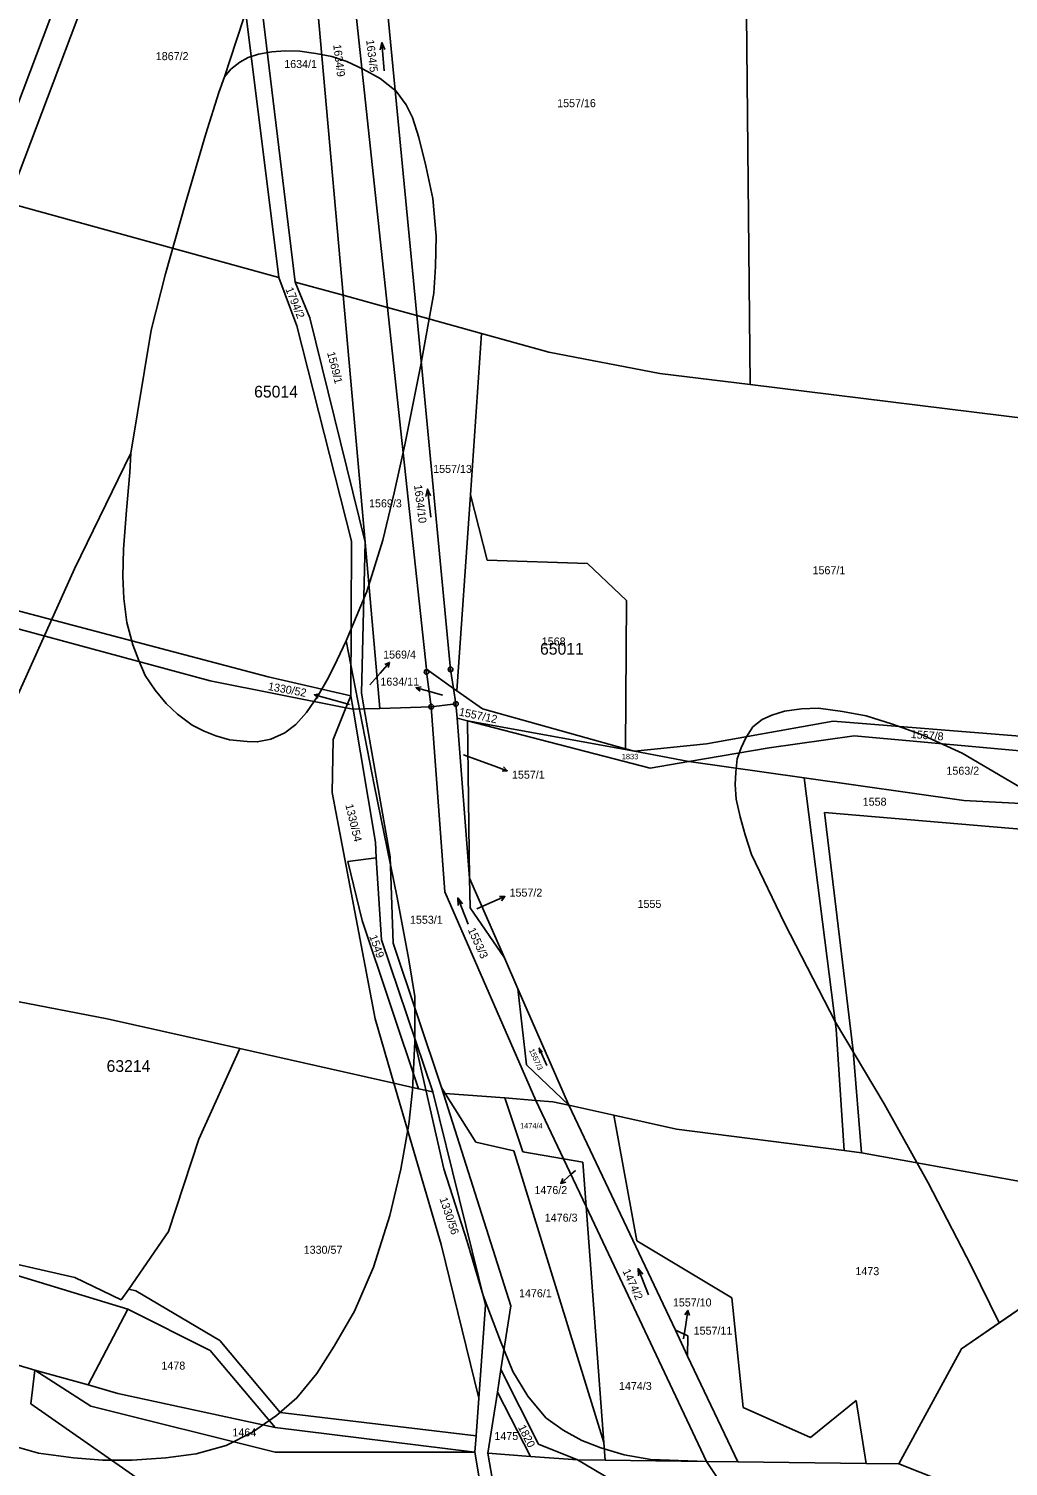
# Model space of a CAD drawing. Extents: x -546762 to -540209, y -1046851 to -1035694.
# Drawn here: x -542518.2 to -542310.2, y -1041335.5 to -1041030.2 of the extents above; entities that cross this region are included whole.
import ezdxf

# ---------------------------------------------------------------- set-up
doc = ezdxf.new("R2010")
doc.units = 0
for name, color, linetype in [('Vrstva 1', 7, 'Continuous'), ('Vrstva 16', 7, 'Continuous'), ('Vrstva 18', 7, 'Continuous'), ('Vrstva 24', 7, 'Continuous'), ('Vrstva 25', 7, 'Continuous'), ('Vrstva 52', 7, 'Continuous'), ('Vrstva 53', 7, 'Continuous'), ('Vrstva 6', 7, 'Continuous')]:
    doc.layers.add(name, color=color, linetype=linetype)

msp = doc.modelspace()

# ---------------------------------------------------------------- linework, layer by layer
at = {"layer": 'Vrstva 1'}
msp.add_line((-542445.44, -1040991.01), (-542435.86, -1041091.16), dxfattribs=at)
for points in [[(-542465.12, -1041083.07), (-542476.38, -1040992.91)], [(-542461.68, -1041084.02), (-542472.7, -1040992.93)], [(-542459.8, -1040992.99), (-542451.48, -1041086.84)], [(-542442.07, -1041089.44), (-542452.43, -1040992.98)], [(-542502.42, -1040998.17), (-542527.98, -1041065.76)], [(-542522.68, -1041067.22), (-542498.43, -1041002.85)], [(-542366.02, -1041005.65), (-542365.01, -1041105.81)], [(-542465.12, -1041083.07), (-542522.68, -1041067.22)], [(-542465.12, -1041083.07), (-542461.35, -1041093.33)], [(-542461.68, -1041084.02), (-542451.48, -1041086.84)], [(-542461.68, -1041084.02), (-542458.58, -1041091.62)], [(-542451.48, -1041086.84), (-542442.07, -1041089.44)], [(-542451.48, -1041086.84), (-542446.83, -1041139.28)], [(-542442.07, -1041089.44), (-542435.86, -1041091.16)], [(-542433.81, -1041166.25), (-542442.07, -1041089.44)], [(-542461.35, -1041093.33), (-542449.71, -1041139.07)], [(-542458.58, -1041091.62), (-542446.83, -1041139.28)], [(-542435.86, -1041091.16), (-542428.67, -1041166.28)], [(-542449.71, -1041139.07), (-542449.85, -1041171.87)], [(-542446.83, -1041139.28), (-542447.57, -1041171.34)], [(-542446.83, -1041139.28), (-542443.7, -1041174.57)], [(-542433.81, -1041166.25), (-542428.03, -1041170.33)], [(-542433.75, -1041166.83), (-542433.81, -1041166.25)], [(-542433.75, -1041166.83), (-542432.78, -1041174.22)], [(-542428.03, -1041170.33), (-542428.67, -1041166.28)], [(-542427.52, -1041173.6), (-542428.03, -1041170.33)], [(-542449.85, -1041171.87), (-542449.37, -1041174.76)], [(-542447.57, -1041171.34), (-542446.99, -1041174.68)], [(-542446.99, -1041174.68), (-542449.37, -1041174.76)], [(-542449.37, -1041174.76), (-542444.64, -1041202.96)], [(-542443.7, -1041174.57), (-542446.99, -1041174.68)], [(-542446.99, -1041174.68), (-542441.5, -1041206.12)], [(-542432.78, -1041174.22), (-542443.7, -1041174.57)], [(-542432.78, -1041174.22), (-542427.52, -1041173.6)], [(-542432.78, -1041174.22), (-542429.91, -1041213.54)], [(-542427.52, -1041173.6), (-542427.28, -1041176.61)], [(-542427.28, -1041176.61), (-542424.63, -1041210.6)], [(-542444.64, -1041202.96), (-542444.44, -1041206.3)], [(-542450.49, -1041207.08), (-542444.44, -1041206.3)], [(-542447.43, -1041219.58), (-542450.49, -1041207.08)], [(-542444.44, -1041206.3), (-542443.37, -1041223.72)], [(-542440.88, -1041224.45), (-542441.5, -1041206.12)], [(-542424.63, -1041210.6), (-542424.54, -1041216.94)], [(-542424.63, -1041210.6), (-542417.24, -1041227.53)], [(-542429.91, -1041213.54), (-542410.53, -1041257.81)], [(-542424.54, -1041216.94), (-542417.24, -1041227.53)], [(-542447.43, -1041219.58), (-542435.45, -1041255.33)], [(-542443.37, -1041223.72), (-542432.45, -1041256)], [(-542440.88, -1041224.45), (-542430.58, -1041255.09)], [(-542417.24, -1041227.53), (-542414.37, -1041234.11)], [(-542412.55, -1041250.28), (-542414.37, -1041234.11)], [(-542414.37, -1041234.11), (-542403.56, -1041258.84)], [(-542501.61, -1041240.47), (-542526.92, -1041235.63)], [(-542473.45, -1041246.8), (-542501.61, -1041240.47)], [(-542473.45, -1041246.8), (-542482.11, -1041266.04)], [(-542403.56, -1041258.84), (-542412.55, -1041250.28)], [(-542432.45, -1041256), (-542435.45, -1041255.33)], [(-542430.58, -1041255.09), (-542415.87, -1041301.43)], [(-542429.81, -1041256.32), (-542430.58, -1041255.09)], [(-542432.45, -1041256), (-542421.27, -1041301.29)], [(-542429.81, -1041256.32), (-542417.16, -1041257.3)], [(-542423.31, -1041266.65), (-542429.81, -1041256.32)], [(-542417.16, -1041257.3), (-542410.53, -1041257.81)], [(-542417.16, -1041257.3), (-542413.31, -1041268.71)], [(-542410.53, -1041257.81), (-542406.92, -1041258.09)], [(-542410.53, -1041257.81), (-542404.68, -1041270.2)], [(-542406.92, -1041258.09), (-542403.56, -1041258.84)], [(-542403.56, -1041258.84), (-542380.93, -1041306.59)], [(-542482.11, -1041266.04), (-542488.54, -1041285.62)], [(-542423.31, -1041266.65), (-542415.21, -1041268.54)], [(-542415.21, -1041268.54), (-542396.14, -1041330.47)], [(-542404.68, -1041270.2), (-542413.31, -1041268.71)], [(-542400.59, -1041270.9), (-542404.68, -1041270.2)], [(-542404.68, -1041270.2), (-542399.88, -1041280.36)], [(-542400.59, -1041270.9), (-542399.88, -1041280.36)], [(-542399.88, -1041280.36), (-542396.14, -1041330.47)], [(-542399.88, -1041280.36), (-542374.33, -1041334.47)], [(-542488.54, -1041285.62), (-542497.03, -1041297.9)], [(-542521.22, -1041292.55), (-542508.43, -1041295.42)], [(-542508.43, -1041295.42), (-542498.6, -1041300.18)], [(-542320.17, -1041310.54), (-542295.33, -1041293.52)], [(-542497.03, -1041297.9), (-542498.6, -1041300.18)], [(-542421.27, -1041301.29), (-542422.69, -1041321.03)], [(-542415.87, -1041301.43), (-542417.97, -1041314.94)], [(-542380.93, -1041306.59), (-542378.32, -1041312.1)], [(-542333.5, -1041335), (-542320.17, -1041310.54)], [(-542378.32, -1041312.1), (-542367.67, -1041334.56)], [(-542417.97, -1041314.94), (-542418.72, -1041319.77)], [(-542417.97, -1041314.94), (-542410, -1041330.82)], [(-542418.72, -1041319.77), (-542420.74, -1041332.76)], [(-542418.72, -1041319.77), (-542411.7, -1041333.4)], [(-542422.69, -1041321.03), (-542423.26, -1041329.04)], [(-542423.26, -1041329.04), (-542423.51, -1041332.52)], [(-542410, -1041330.82), (-542401.69, -1041334.11)], [(-542396.14, -1041330.47), (-542395.87, -1041334.19)], [(-542423.51, -1041332.52), (-542417.02, -1041371.37)], [(-542411.7, -1041333.4), (-542420.74, -1041332.76)], [(-542420.74, -1041332.76), (-542414.26, -1041370.41)], [(-542401.69, -1041334.11), (-542411.7, -1041333.4)], [(-542395.87, -1041334.19), (-542401.69, -1041334.11)], [(-542374.33, -1041334.47), (-542395.87, -1041334.19)], [(-542367.67, -1041334.56), (-542374.33, -1041334.47)], [(-542374.33, -1041334.47), (-542345.88, -1041377.29)], [(-542340.44, -1041334.91), (-542367.67, -1041334.56)], [(-542333.5, -1041335), (-542340.44, -1041334.91)]]:
    msp.add_lwpolyline(points, dxfattribs=at)
at = {"layer": 'Vrstva 16'}
for p, q in [((-542443.59, -1041167.06), (-542441.61, -1041164.81)), ((-542433.09, -1041171.01), (-542435.98, -1041170.19)), ((-542454.7, -1041172.47), (-542457.59, -1041171.65)), ((-542419.45, -1041186.76), (-542416.63, -1041187.79)), ((-542419.89, -1041215.74), (-542417.14, -1041214.54)), ((-542403.03, -1041273.46), (-542405.28, -1041275.44)), ((-542378.73, -1041305.37), (-542378.25, -1041302.41))]:
    msp.add_line(p, q, dxfattribs=at)
for points in [[(-542445.78, -1041169.55), (-542443.59, -1041167.06)], [(-542442.64, -1041165.23), (-542441.61, -1041164.81), (-542441.89, -1041165.89)], [(-542435.15, -1041170.94), (-542435.98, -1041170.19), (-542434.88, -1041169.98)], [(-542456.76, -1041172.41), (-542457.59, -1041171.65), (-542456.49, -1041171.44)], [(-542450.13, -1041173.76), (-542454.7, -1041172.47)], [(-542430.38, -1041171.78), (-542433.09, -1041171.01)], [(-542425.89, -1041184.42), (-542419.45, -1041186.76)], [(-542417.4, -1041186.97), (-542416.63, -1041187.79), (-542417.74, -1041187.91)], [(-542423.07, -1041217.13), (-542419.89, -1041215.74)], [(-542418.26, -1041214.48), (-542417.14, -1041214.54), (-542417.86, -1041215.4)], [(-542402.15, -1041272.68), (-542403.03, -1041273.46)], [(-542404.2, -1041275.16), (-542405.28, -1041275.44), (-542404.86, -1041274.41)], [(-542378.91, -1041303.32), (-542378.25, -1041302.41), (-542377.92, -1041303.48)], [(-542379.22, -1041308.43), (-542378.73, -1041305.37)]]:
    msp.add_lwpolyline(points, dxfattribs=at)
at = {"layer": 'Vrstva 24'}
for centre, radius in [((-542433.75, -1041166.83), 0.5), ((-542433.75, -1041166.83), 0.1), ((-542428.67, -1041166.28), 0.5), ((-542428.67, -1041166.28), 0.1), ((-542427.52, -1041173.6), 0.5), ((-542427.52, -1041173.6), 0.1), ((-542432.78, -1041174.22), 0.5), ((-542432.78, -1041174.22), 0.1)]:
    msp.add_circle(centre, radius, dxfattribs=at)
at = {"layer": 'Vrstva 25'}
for points in [[(-542442.76, -1041039.17), (-542443.26, -1041033.19), (-542443.63, -1041034.73)], [(-542443.26, -1041033.19), (-542442.64, -1041034.64)], [(-542432.84, -1041133.95), (-542433.6, -1041127.99), (-542433.9, -1041129.54)], [(-542433.6, -1041127.99), (-542432.91, -1041129.42)], [(-542424.94, -1041220.41), (-542427.14, -1041214.83), (-542427.05, -1041216.41)], [(-542427.14, -1041214.83), (-542426.12, -1041216.04)], [(-542408.22, -1041250.39), (-542409.84, -1041246.71), (-542409.74, -1041247.77)], [(-542409.84, -1041246.71), (-542409.13, -1041247.5)], [(-542386.62, -1041299.08), (-542388.86, -1041293.52), (-542388.77, -1041295.1)], [(-542388.86, -1041293.52), (-542387.84, -1041294.72)]]:
    msp.add_lwpolyline(points, dxfattribs=at)
at = {"layer": 'Vrstva 52'}
for points in [[(-542476.71, -1041040.42), (-542475.45, -1041036.75), (-542472.54, -1041027.9), (-542469.63, -1041016.88), (-542458.71, -1040980.09)], [(-542476.71, -1041040.42), (-542475.34, -1041038.82), (-542473.45, -1041037.32), (-542471.63, -1041036.37), (-542469.45, -1041035.62), (-542466.64, -1041035.15), (-542463.81, -1041034.94), (-542460.69, -1041035.01)], [(-542460.69, -1041035.01), (-542457.3, -1041035.5), (-542453.91, -1041036.12), (-542450.73, -1041037.16), (-542447.2, -1041038.82), (-542443.6, -1041040.83), (-542440.21, -1041043.46), (-542438.13, -1041046.37), (-542436.75, -1041049.07), (-542435.38, -1041053.31), (-542433.93, -1041059.37), (-542432.47, -1041066.28), (-542431.75, -1041074.27), (-542431.87, -1041080.7), (-542432.19, -1041086.37), (-542434.97, -1041101.64), (-542438.36, -1041118.6), (-542440.66, -1041128.78), (-542443.08, -1041138.84), (-542446.48, -1041149.74), (-542450.83, -1041160.24)], [(-542496.58, -1041120.37), (-542492.24, -1041094.27), (-542489.21, -1041082.27), (-542484.98, -1041067.25), (-542480.62, -1041052.58), (-542477.87, -1041043.78), (-542476.71, -1041040.42)], [(-542553.39, -1041234.34), (-542551.08, -1041232.04), (-542548.12, -1041228.43), (-542544, -1041220.92), (-542531.53, -1041195.96), (-542508.52, -1041144.95), (-542496.58, -1041120.37)], [(-542496.58, -1041120.37), (-542496.79, -1041124.48)], [(-542496.79, -1041124.48), (-542497.48, -1041132.45), (-542498.11, -1041140.75), (-542498.3, -1041146.57), (-542498.09, -1041151.21), (-542497.4, -1041156.33), (-542496.15, -1041161.04), (-542494.9, -1041164.37), (-542493.52, -1041167.55), (-542491.38, -1041170.67), (-542489.09, -1041173.51), (-542486.67, -1041175.79), (-542483.56, -1041178.15), (-542480.99, -1041179.39), (-542478.5, -1041180.36), (-542475.6, -1041181.26), (-542471.86, -1041181.61), (-542469.71, -1041181.68), (-542466.81, -1041181.12), (-542463.83, -1041179.74), (-542461.55, -1041178.01), (-542459.26, -1041175.44), (-542456.77, -1041171.84), (-542454.84, -1041168.52), (-542453.38, -1041165.61), (-542450.83, -1041160.24)], [(-542450.83, -1041160.24), (-542444.9, -1041190.78), (-542440.02, -1041214.74), (-542437.5, -1041227.98), (-542436.28, -1041235.73), (-542436.28, -1041245.31)], [(-542312.19, -1041305.07), (-542318.13, -1041292.92), (-542327.24, -1041275.32), (-542336.56, -1041258.57), (-542346.95, -1041241.18), (-542357.76, -1041220.19), (-542364.75, -1041205.56), (-542366.09, -1041201.43), (-542367.2, -1041197.56), (-542368.03, -1041193.82), (-542368.23, -1041190.7), (-542368.1, -1041188.14), (-542367.82, -1041185.3), (-542366.99, -1041182.95), (-542365.95, -1041180.8), (-542364.5, -1041178.51), (-542362.49, -1041176.92), (-542360.41, -1041176.02), (-542357.78, -1041175.12), (-542354.12, -1041174.64), (-542350.52, -1041174.5), (-542345.4, -1041175.19)], [(-542345.4, -1041175.19), (-542340.41, -1041176.16), (-542334.81, -1041177.89), (-542328.86, -1041180.04), (-542320, -1041184.05), (-542309.9, -1041190.01), (-542295.43, -1041198.52), (-542278.04, -1041209.74), (-542265.45, -1041220.04), (-542255.28, -1041229.01), (-542248.36, -1041236.69), (-542242.42, -1041245.17), (-542237.82, -1041253.89), (-542232.09, -1041268.86)], [(-542436.28, -1041245.31), (-542436.77, -1041255.61), (-542437.5, -1041262.88), (-542439.25, -1041272.42), (-542441.55, -1041282.23), (-542445.06, -1041293.26), (-542449.06, -1041302.59), (-542453.42, -1041309.98), (-542457.05, -1041315.8), (-542461.29, -1041321.01), (-542465.65, -1041324.76), (-542470.74, -1041328.28), (-542476.31, -1041331.07), (-542482.73, -1041332.88), (-542489.15, -1041333.73), (-542496.29, -1041334.22), (-542502.59, -1041334.22), (-542508.77, -1041333.73), (-542516.15, -1041332.76), (-542521.6, -1041331.19)], [(-542436.28, -1041245.31), (-542430.09, -1041272.37), (-542425.12, -1041287.76), (-542421.73, -1041299.27), (-542418.1, -1041308.96), (-542415.43, -1041315.39), (-542412.28, -1041320.6), (-542408.41, -1041325.2), (-542404.77, -1041327.87), (-542400.78, -1041330.05), (-542396.78, -1041331.62), (-542391.82, -1041333.08), (-542386.12, -1041334.05), (-542374.33, -1041334.47)], [(-542232.09, -1041268.86), (-542236.18, -1041270.16), (-542242.64, -1041273.68), (-542249.01, -1041275.7), (-542269.97, -1041277.3), (-542277.64, -1041275.35), (-542284.6, -1041276.02), (-542285.23, -1041279.09), (-542295.33, -1041293.52), (-542312.19, -1041305.07)], [(-542312.19, -1041305.07), (-542320.17, -1041310.54), (-542333.5, -1041335), (-542340.44, -1041334.91), (-542367.67, -1041334.56), (-542374.33, -1041334.47)], [(-542374.33, -1041334.47), (-542345.88, -1041377.29), (-542319.7, -1041412.45), (-542323.13, -1041412.45), (-542321.53, -1041414.69), (-542314.85, -1041424.04), (-542313.06, -1041426.54)]]:
    msp.add_lwpolyline(points, dxfattribs=at)
at = {"layer": 'Vrstva 6'}
for points in [[(-542435.86, -1041091.16), (-542422.07, -1041094.98)], [(-542422.07, -1041094.98), (-542424.46, -1041129.19)], [(-542422.07, -1041094.98), (-542407.78, -1041098.94)], [(-542407.78, -1041098.94), (-542384.24, -1041103.43)], [(-542384.24, -1041103.43), (-542365.01, -1041105.81)], [(-542365.01, -1041105.81), (-542299.72, -1041113.88)], [(-542424.46, -1041129.19), (-542427.35, -1041170.81)], [(-542424.46, -1041129.19), (-542420.91, -1041143.07)], [(-542399.61, -1041143.77), (-542420.91, -1041143.07)], [(-542391.32, -1041151.68), (-542399.61, -1041143.77)], [(-542545.5, -1041147.28), (-542467.44, -1041167.89)], [(-542545.67, -1041150.84), (-542479.74, -1041168.68)], [(-542391.5, -1041183.14), (-542391.32, -1041151.68)], [(-542479.74, -1041168.68), (-542450.9, -1041174.45)], [(-542467.44, -1041167.89), (-542449.85, -1041171.87)], [(-542427.35, -1041170.81), (-542428.03, -1041170.33)], [(-542449.85, -1041171.87), (-542450.9, -1041174.45)], [(-542427.35, -1041170.81), (-542421.87, -1041174.68)], [(-542450.9, -1041174.45), (-542453.61, -1041181.17)], [(-542450.9, -1041174.45), (-542449.37, -1041174.76)], [(-542425.1, -1041177.18), (-542427.28, -1041176.61)], [(-542421.87, -1041174.68), (-542391.5, -1041183.14)], [(-542386.29, -1041187.27), (-542425.1, -1041177.18)], [(-542425.1, -1041177.18), (-542424.63, -1041210.6)], [(-542425.1, -1041177.18), (-542389.61, -1041183.67)], [(-542374.33, -1041182.06), (-542347.45, -1041177.3)], [(-542347.45, -1041177.3), (-542278.59, -1041182.79)], [(-542453.61, -1041181.17), (-542453.78, -1041192.44)], [(-542389.61, -1041183.67), (-542374.33, -1041182.06)], [(-542361.04, -1041182.97), (-542342.98, -1041180.37)], [(-542342.98, -1041180.37), (-542274.11, -1041186.62)], [(-542391.5, -1041183.14), (-542389.61, -1041183.67)], [(-542389.61, -1041183.67), (-542378.07, -1041185.87)], [(-542361.04, -1041182.97), (-542378.07, -1041185.87)], [(-542378.07, -1041185.87), (-542386.29, -1041187.27)], [(-542353.57, -1041189.34), (-542378.07, -1041185.87)], [(-542319.69, -1041194.14), (-542353.57, -1041189.34)], [(-542346.81, -1041242.67), (-542353.57, -1041189.34)], [(-542453.78, -1041192.44), (-542444.69, -1041240.47)], [(-542275.04, -1041196.43), (-542319.69, -1041194.14)], [(-542343.15, -1041247.26), (-542349.23, -1041196.67)], [(-542277.6, -1041202.78), (-542349.23, -1041196.67)], [(-542444.69, -1041240.47), (-542440.69, -1041254.16)], [(-542345.06, -1041268.46), (-542346.81, -1041242.67)], [(-542473.45, -1041246.8), (-542440.69, -1041254.16)], [(-542341.38, -1041268.93), (-542343.15, -1041247.26)], [(-542440.69, -1041254.16), (-542435.45, -1041255.33)], [(-542440.69, -1041254.16), (-542430.65, -1041288.42)], [(-542403.56, -1041258.84), (-542394.03, -1041260.97)], [(-542394.03, -1041260.97), (-542380.7, -1041263.94)], [(-542394.03, -1041260.97), (-542389.13, -1041287.61)], [(-542380.7, -1041263.94), (-542345.06, -1041268.46)], [(-542345.06, -1041268.46), (-542341.38, -1041268.93)], [(-542341.38, -1041268.93), (-542285.23, -1041279.09)], [(-542430.65, -1041288.42), (-542422.69, -1041321.03)], [(-542389.13, -1041287.61), (-542368.97, -1041299.72)], [(-542522.52, -1041294.41), (-542497.22, -1041302.14)], [(-542497.03, -1041297.9), (-542495.51, -1041298.23)], [(-542495.51, -1041298.23), (-542477.65, -1041308.8)], [(-542368.97, -1041299.72), (-542366.54, -1041323.04)], [(-542505.66, -1041318.25), (-542497.22, -1041302.14)], [(-542497.22, -1041302.14), (-542479.71, -1041310.9)], [(-542378.27, -1041307.81), (-542380.93, -1041306.59)], [(-542378.27, -1041307.81), (-542378.32, -1041312.1)], [(-542479.71, -1041310.9), (-542465.92, -1041327.3)], [(-542477.65, -1041308.8), (-542464.89, -1041324.09)], [(-542528.42, -1041311.68), (-542516.94, -1041315.11)], [(-542516.94, -1041315.11), (-542517.84, -1041322.27)], [(-542505.05, -1041322.76), (-542516.94, -1041315.11)], [(-542516.94, -1041315.11), (-542505.66, -1041318.25)], [(-542505.66, -1041318.25), (-542499.3, -1041320.02)], [(-542499.3, -1041320.02), (-542465.92, -1041327.3)], [(-542517.84, -1041322.27), (-542489.4, -1041342.05)], [(-542505.05, -1041322.76), (-542465.94, -1041332.49)], [(-542366.54, -1041323.04), (-542352.2, -1041329.37)], [(-542352.2, -1041329.37), (-542342.5, -1041321.56)], [(-542340.44, -1041334.91), (-542342.5, -1041321.56)], [(-542464.89, -1041324.09), (-542423.26, -1041329.04)], [(-542465.92, -1041327.3), (-542423.51, -1041332.52)], [(-542465.94, -1041332.49), (-542423.51, -1041332.52)], [(-542401.69, -1041334.11), (-542389.07, -1041341.63)], [(-542333.5, -1041335), (-542310.47, -1041344.13)]]:
    msp.add_lwpolyline(points, dxfattribs=at)

# ---------------------------------------------------------------- texts
at = {"layer": 'Vrstva 16'}
for s, p in [('1569/4', (-542442.98, -1041163.98)), ('1634/11', (-542443.57, -1041169.73)), ('1557/1', (-542415.63, -1041189.49)), ('1557/2', (-542416.14, -1041214.54)), ('1476/2', (-542410.85, -1041277.71)), ('1557/10', (-542381.46, -1041301.57))]:
    msp.add_text(s, height=1.7, dxfattribs=at).set_placement(p)
msp.add_text('1330/52', height=1.7, rotation=349.5736, dxfattribs=at).set_placement((-542467.53, -1041170.65))
at = {"layer": 'Vrstva 18'}
for s, height, rotation, p in [('1634/5', 1.7, 276.7801, (-542446.6, -1041032.65)), ('1634/9', 1.7, 277.1813, (-542453.6, -1041033.64)), ('1794/2', 1.7, 292.1445, (-542463.77, -1041085.52)), ('1569/1', 1.7, 284.2725, (-542454.91, -1041099.03)), ('1634/10', 1.7, 277.1816, (-542436.43, -1041127.17)), ('1557/12', 1.7, 347.9454, (-542426.99, -1041176.04)), ('1557/8', 1.7, 355.4724, (-542330.98, -1041180.84)), ('1330/54', 1.7, 283.5709, (-542451.03, -1041195.07)), ('1553/3', 1.7, 294.6282, (-542425.06, -1041221.57)), ('1549', 1.7, 289.2411, (-542445.95, -1041222.98)), ('1557/3', 1.14, 294.5596, (-542412.04, -1041247.15)), ('1330/56', 1.7, 288.4911, (-542431.04, -1041278.7)), ('1474/2', 1.7, 294.7726, (-542392.19, -1041294.07)), ('1820', 1.7, 296.7288, (-542414.4, -1041327.21))]:
    msp.add_text(s, height=height, rotation=rotation, dxfattribs=at).set_placement(p)
for s, height, p in [('1867/2', 1.7, (-542491.27, -1041036.9)), ('1634/1', 1.7, (-542463.99, -1041038.57)), ('1557/16', 1.7, (-542406.03, -1041046.89)), ('1557/13', 1.7, (-542432.36, -1041124.56)), ('1569/3', 1.7, (-542445.98, -1041131.87)), ('1567/1', 1.7, (-542351.79, -1041146.08)), ('1568', 1.7, (-542409.3, -1041161.2)), ('1569/4', 0.1, (-542445.99, -1041169.55)), ('1634/11', 0.1, (-542430.6, -1041171.78)), ('1330/52', 0.1, (-542450.38, -1041173.76)), ('1557/1', 0.1, (-542426.08, -1041184.42)), ('1833', 1.14, (-542392.31, -1041185.36)), ('1563/2', 1.7, (-542323.36, -1041188.65)), ('1558', 1.7, (-542341.14, -1041195.23)), ('1555', 1.7, (-542388.96, -1041216.93)), ('1553/1', 1.7, (-542437.29, -1041220.3)), ('1557/2', 0.1, (-542423.28, -1041217.13)), ('1474/4', 1.14, (-542413.92, -1041263.77)), ('1476/2', 0.1, (-542402.36, -1041272.68)), ('1476/3', 1.7, (-542408.66, -1041283.56)), ('1330/57', 1.7, (-542459.86, -1041290.38)), ('1473', 1.7, (-542342.69, -1041294.92)), ('1476/1', 1.7, (-542414.13, -1041299.62)), ('1557/11', 1.7, (-542377.04, -1041307.56)), ('1557/10', 0.1, (-542379.46, -1041308.43)), ('1478', 1.7, (-542490.07, -1041314.98)), ('1474/3', 1.7, (-542392.9, -1041319.31)), ('1464', 1.7, (-542475, -1041329.17)), ('1475', 1.7, (-542419.36, -1041329.93))]:
    msp.add_text(s, height=height, dxfattribs=at).set_placement(p)
at = {"layer": 'Vrstva 53'}
for s, p in [('65014', (-542470.38, -1041108.55)), ('65011', (-542409.67, -1041163.16)), ('63214', (-542501.72, -1041251.76))]:
    msp.add_text(s, height=2.5, dxfattribs=at).set_placement(p)

doc.saveas('drawing.dxf')
